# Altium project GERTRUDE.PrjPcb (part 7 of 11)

## Sheet MICROCONTROLLER.SchDoc: Microcontroller
size A3; SheetNumber: 11; SheetTotal: 51
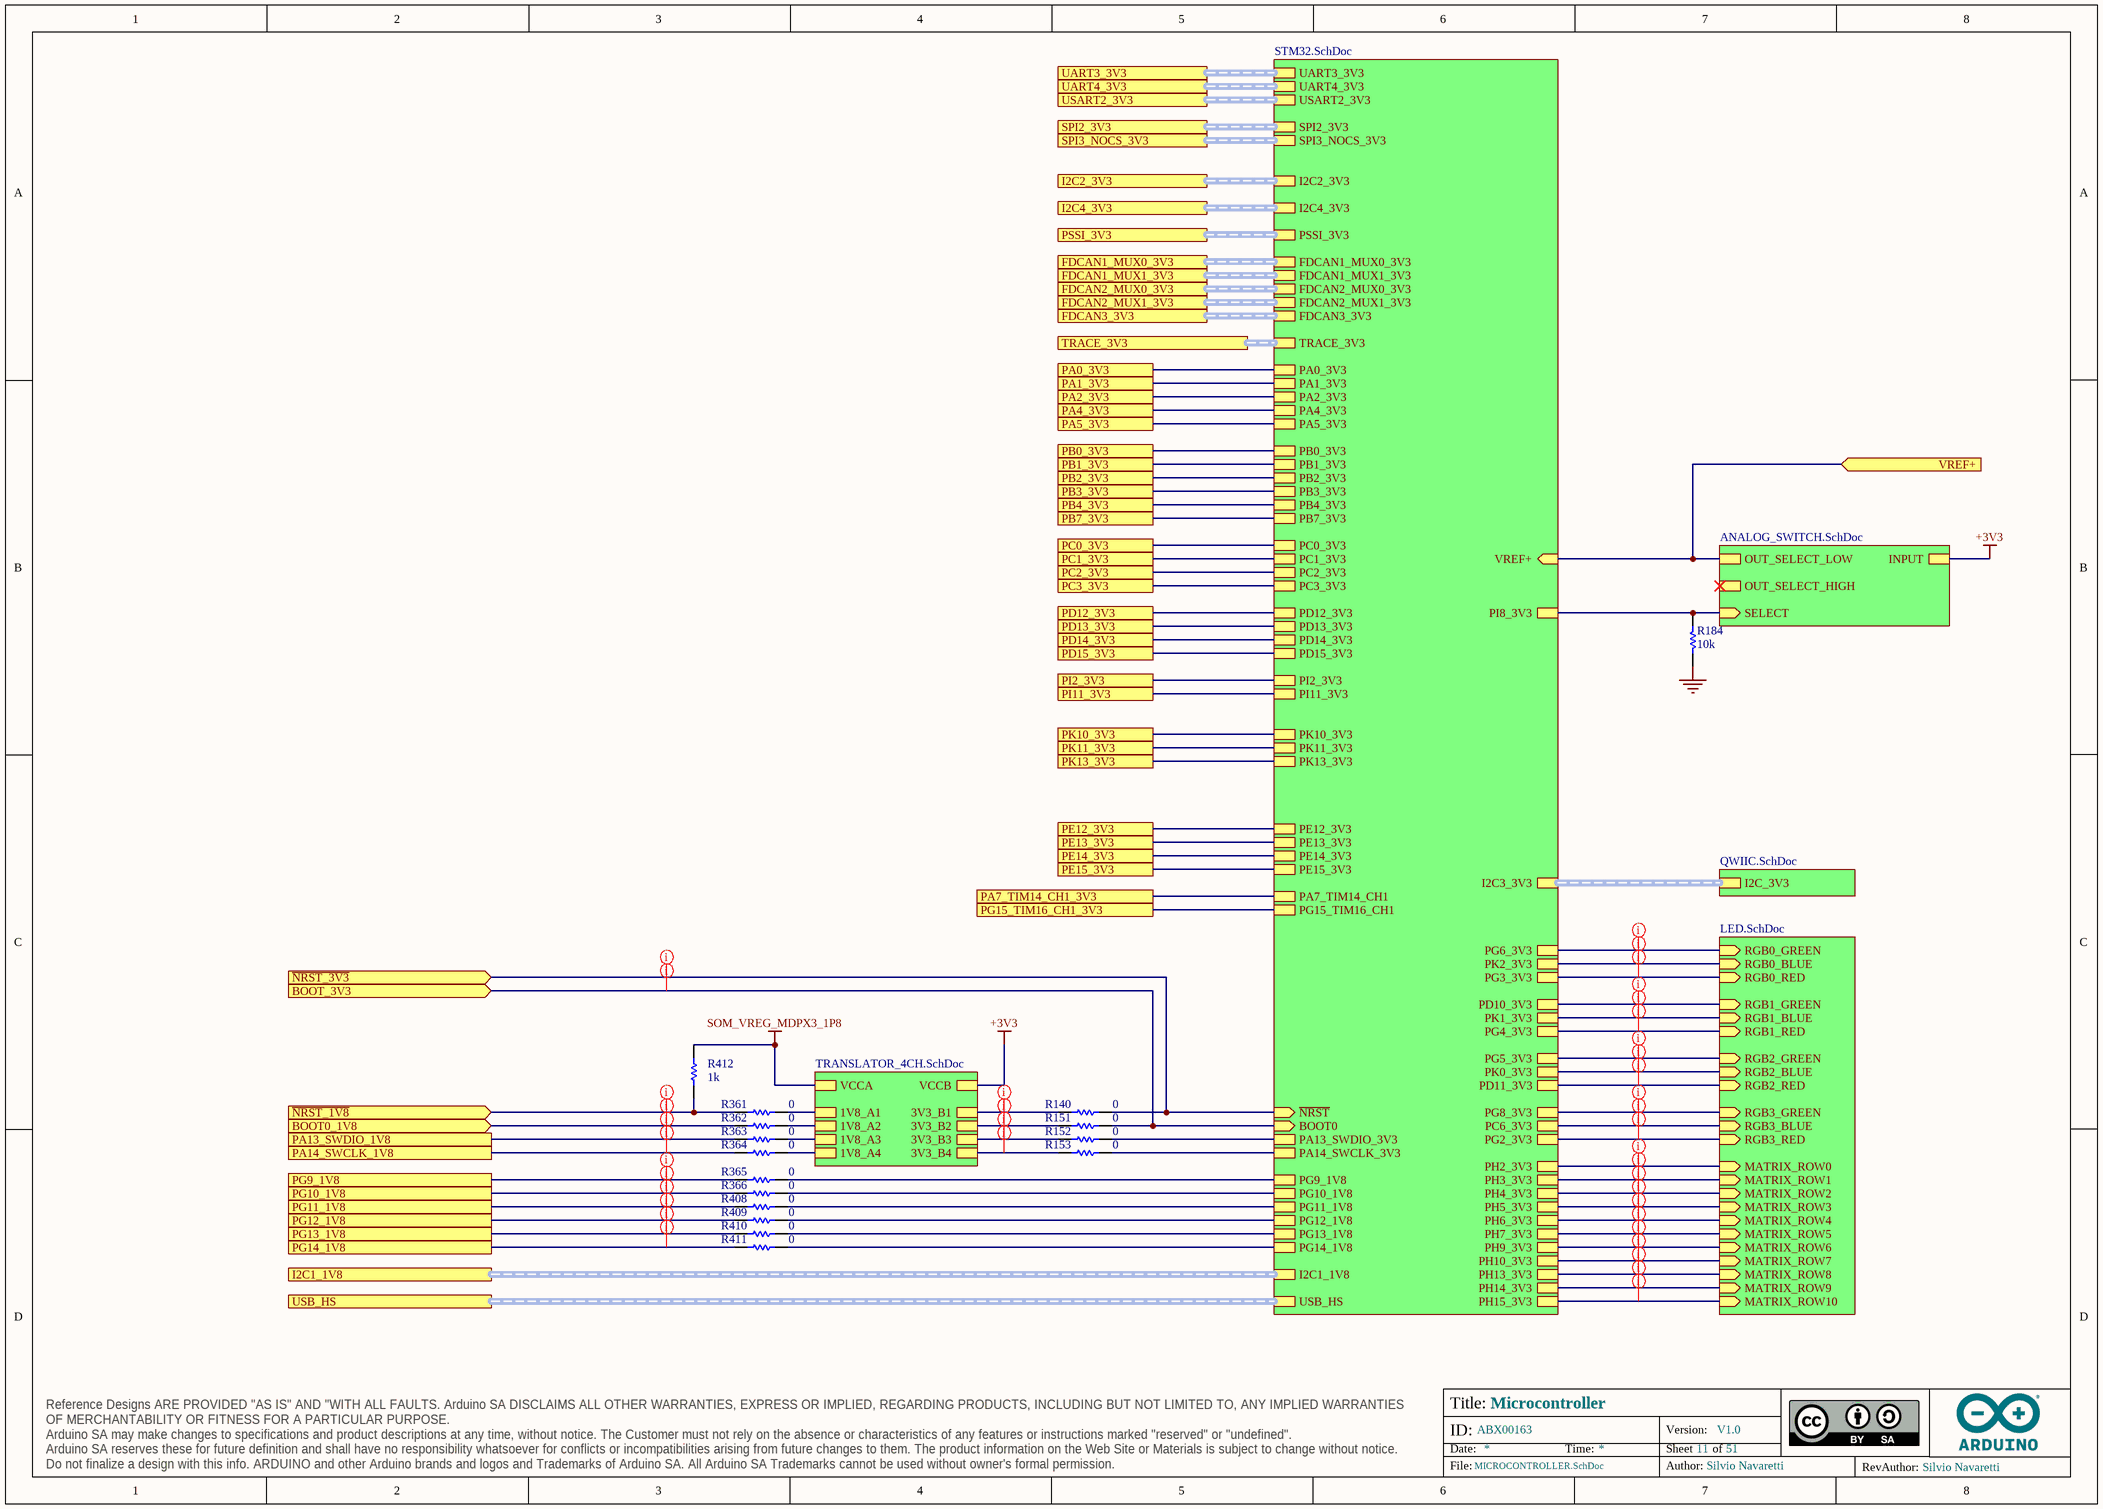
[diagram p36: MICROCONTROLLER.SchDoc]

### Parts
R140  value 0  [RES-0201]  (hidden comment: CRCW02010000Z0ED)
R151  value 0  [RES-0201]  (hidden comment: CRCW02010000Z0ED)
R152  value 0  [RES-0201]  (hidden comment: CRCW02010000Z0ED)
R153  value 0  [RES-0201]  (hidden comment: CRCW02010000Z0ED)
R184  value 10k  [RES-0201]  (hidden comment: RC0201FR-0710KL)
R361  value 0  [RES-0201]  (hidden comment: CRCW02010000Z0ED)
R362  value 0  [RES-0201]  (hidden comment: CRCW02010000Z0ED)
R363  value 0  [RES-0201]  (hidden comment: CRCW02010000Z0ED)
R364  value 0  [RES-0201]  (hidden comment: CRCW02010000Z0ED)
R365  value 0  [RES-0201]  (hidden comment: CRCW02010000Z0ED)
R366  value 0  [RES-0201]  (hidden comment: CRCW02010000Z0ED)
R408  value 0  [RES-0201]  (hidden comment: CRCW02010000Z0ED)
R409  value 0  [RES-0201]  (hidden comment: CRCW02010000Z0ED)
R410  value 0  [RES-0201]  (hidden comment: CRCW02010000Z0ED)
R411  value 0  [RES-0201]  (hidden comment: CRCW02010000Z0ED)
R412  value 1k  [RES-0201]  (hidden comment: RC0201FR-071KL)

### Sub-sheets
U_ANALOG_SWITCH = ANALOG_SWITCH.SchDoc: SELECT (in), OUT_SELECT_LOW, OUT_SELECT_HIGH, INPUT
U_LED = LED.SchDoc: RGB0_GREEN (in), RGB0_BLUE (in), RGB0_RED (in), RGB1_GREEN (in), RGB1_BLUE (in), RGB1_RED (in), RGB2_GREEN (in), RGB2_BLUE (in), RGB2_RED (in), RGB3_GREEN (in), RGB3_BLUE (in), RGB3_RED (in), MATRIX_ROW0 (in), MATRIX_ROW1 (in), MATRIX_ROW2 (in), MATRIX_ROW3 (in), MATRIX_ROW4 (in), MATRIX_ROW5 (in), MATRIX_ROW6 (in), MATRIX_ROW7 (in), MATRIX_ROW8 (in), MATRIX_ROW9 (in), MATRIX_ROW10 (in)
U_QWIIC = QWIIC.SchDoc: I2C_3V3 (harness I2C)
U_STM32 = STM32.SchDoc: USB_HS (harness SOM_MD_USB1), ~{NRST} (in), BOOT0 (in), UART3_3V3 (harness UART), PB2_3V3, PB3_3V3, FDCAN2_MUX0_3V3 (harness CAN), PB0_3V3, PB1_3V3, PB4_3V3, PB7_3V3, SPI2_3V3 (harness SPI), PA0_3V3, PA1_3V3, I2C2_3V3 (harness I2C), PA2_3V3, UART4_3V3 (harness UART), PSSI_3V3 (harness PSSI), PA4_3V3, PA5_3V3, PE12_3V3, PE13_3V3, PE14_3V3, PE15_3V3, FDCAN1_MUX0_3V3 (harness CAN), FDCAN2_MUX1_3V3 (harness CAN), PC0_3V3, PC1_3V3, PC2_3V3, PC3_3V3, PH2_3V3, PH3_3V3, PH4_3V3, PH5_3V3, PH6_3V3, PH7_3V3, PH9_3V3, PH13_3V3, PH14_3V3, PH15_3V3, VREF+ (in), SPI3_NOCS_3V3 (harness JSPI_SPI), I2C4_3V3 (harness I2C), PG9_1V8, PG10_1V8, PG11_1V8, PG12_1V8, PG13_1V8, PG14_1V8, I2C3_3V3 (harness I2C), I2C1_1V8 (harness I2C), PA13_SWDIO_3V3, PA14_SWCLK_3V3, TRACE_3V3 (harness MCU_TRACE), USART2_3V3 (harness UART), PA7_TIM14_CH1, PG15_TIM16_CH1, FDCAN3_3V3 (harness CAN), FDCAN1_MUX1_3V3 (harness CAN), PD12_3V3, PD13_3V3, PD14_3V3, PD15_3V3, PI2_3V3, PI11_3V3, PI8_3V3, PG2_3V3, PK0_3V3, PK1_3V3, PK2_3V3, PD10_3V3, PD11_3V3, PG3_3V3, PG4_3V3, PG5_3V3, PG6_3V3, PC6_3V3, PG8_3V3, PH10_3V3, PK13_3V3, PK10_3V3, PK11_3V3
U_TRANSLATOR_4CH = TRANSLATOR_4CH.SchDoc: 1V8_A1, 1V8_A2, 1V8_A3, 1V8_A4, 3V3_B1, 3V3_B2, 3V3_B3, 3V3_B4, VCCA, VCCB

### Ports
BOOT0_1V8 (in), BOOT_3V3 (in), FDCAN1_MUX0_3V3, FDCAN1_MUX1_3V3, FDCAN2_MUX0_3V3, FDCAN2_MUX1_3V3, FDCAN3_3V3, I2C1_1V8, I2C2_3V3, I2C4_3V3, PA0_3V3, PA1_3V3, PA2_3V3, PA4_3V3, PA5_3V3, PA7_TIM14_CH1_3V3, PA13_SWDIO_1V8, PA14_SWCLK_1V8, PB0_3V3, PB1_3V3, PB2_3V3, PB3_3V3, PB4_3V3, PB7_3V3, PC0_3V3, PC1_3V3, PC2_3V3, PC3_3V3, PD12_3V3, PD13_3V3, PD14_3V3, PD15_3V3, PE12_3V3, PE13_3V3, PE14_3V3, PE15_3V3, PG9_1V8, PG10_1V8, PG11_1V8, PG12_1V8, PG13_1V8, PG14_1V8, PG15_TIM16_CH1_3V3, PI2_3V3, PI11_3V3, PK10_3V3, PK11_3V3, PK13_3V3, PSSI_3V3, SPI2_3V3, SPI3_NOCS_3V3, TRACE_3V3, UART3_3V3, UART4_3V3, USART2_3V3, USB_HS, VREF+ (in), ~{NRST_1V8} (in), ~{NRST_3V3} (in)

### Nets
+3V3: sheet U_ANALOG_SWITCH/INPUT, sheet U_TRANSLATOR_4CH/VCCB
GND: R184.1
SOM_VREG_MDPX3_1P8: R412.1 ; sheet U_TRANSLATOR_4CH/VCCA
BOOT0: R151.1 ; port BOOT_3V3, sheet U_STM32/BOOT0
MD_GPIO_42: R408.2 ; port PG11_1V8
MD_GPIO_47: R362.2 ; port BOOT0_1V8
MD_GPIO_63: R409.2 ; port PG12_1V8
MD_GPIO_69: R365.2 ; port PG9_1V8
MD_GPIO_70: R363.2 ; port PA13_SWDIO_1V8
MD_GPIO_71: R364.2 ; port PA14_SWCLK_1V8
MD_GPIO_78: R361.2 R412.2 ; port ~{NRST_1V8}
MD_GPIO_92: R366.2 ; port PG10_1V8
MD_GPIO_95: R410.2 ; port PG13_1V8
MD_GPIO_96: R411.2 ; port PG14_1V8
NRST: R140.1 ; port ~{NRST_3V3}, sheet U_STM32/~{NRST}
PA0: port PA0_3V3, sheet U_STM32/PA0_3V3
PA1: port PA1_3V3, sheet U_STM32/PA1_3V3
PA2: port PA2_3V3, sheet U_STM32/PA2_3V3
PA4: port PA4_3V3, sheet U_STM32/PA4_3V3
PA5: port PA5_3V3, sheet U_STM32/PA5_3V3
PA7: port PA7_TIM14_CH1_3V3, sheet U_STM32/PA7_TIM14_CH1
PA13: R152.1 ; sheet U_STM32/PA13_SWDIO_3V3
PA14: R153.1 ; sheet U_STM32/PA14_SWCLK_3V3
PB0: port PB0_3V3, sheet U_STM32/PB0_3V3
PB1: port PB1_3V3, sheet U_STM32/PB1_3V3
PB2: port PB2_3V3, sheet U_STM32/PB2_3V3
PB3: port PB3_3V3, sheet U_STM32/PB3_3V3
PB4: port PB4_3V3, sheet U_STM32/PB4_3V3
PB7: port PB7_3V3, sheet U_STM32/PB7_3V3
PC0: port PC0_3V3, sheet U_STM32/PC0_3V3
PC1: port PC1_3V3, sheet U_STM32/PC1_3V3
PC2: port PC2_3V3, sheet U_STM32/PC2_3V3
PC3: port PC3_3V3, sheet U_STM32/PC3_3V3
PC6: sheet U_STM32/PC6_3V3, sheet U_LED/RGB3_BLUE
PD10: sheet U_STM32/PD10_3V3, sheet U_LED/RGB1_GREEN
PD11: sheet U_STM32/PD11_3V3, sheet U_LED/RGB2_RED
PD12: port PD12_3V3, sheet U_STM32/PD12_3V3
PD13: port PD13_3V3, sheet U_STM32/PD13_3V3
PD14: port PD14_3V3, sheet U_STM32/PD14_3V3
PD15: port PD15_3V3, sheet U_STM32/PD15_3V3
PE12: port PE12_3V3, sheet U_STM32/PE12_3V3
PE13: port PE13_3V3, sheet U_STM32/PE13_3V3
PE14: port PE14_3V3, sheet U_STM32/PE14_3V3
PE15: port PE15_3V3, sheet U_STM32/PE15_3V3
PG2: sheet U_STM32/PG2_3V3, sheet U_LED/RGB3_RED
PG3: sheet U_STM32/PG3_3V3, sheet U_LED/RGB0_RED
PG4: sheet U_STM32/PG4_3V3, sheet U_LED/RGB1_RED
PG5: sheet U_STM32/PG5_3V3, sheet U_LED/RGB2_GREEN
PG6: sheet U_STM32/PG6_3V3, sheet U_LED/RGB0_GREEN
PG8: sheet U_STM32/PG8_3V3, sheet U_LED/RGB3_GREEN
PG9: R365.1 ; sheet U_STM32/PG9_1V8
PG10: R366.1 ; sheet U_STM32/PG10_1V8
PG11: R408.1 ; sheet U_STM32/PG11_1V8
PG12: R409.1 ; sheet U_STM32/PG12_1V8
PG13: R410.1 ; sheet U_STM32/PG13_1V8
PG14: R411.1 ; sheet U_STM32/PG14_1V8
PG15: port PG15_TIM16_CH1_3V3, sheet U_STM32/PG15_TIM16_CH1
PH2: sheet U_STM32/PH2_3V3, sheet U_LED/MATRIX_ROW0
PH3: sheet U_STM32/PH3_3V3, sheet U_LED/MATRIX_ROW1
PH4: sheet U_STM32/PH4_3V3, sheet U_LED/MATRIX_ROW2
PH5: sheet U_STM32/PH5_3V3, sheet U_LED/MATRIX_ROW3
PH6: sheet U_STM32/PH6_3V3, sheet U_LED/MATRIX_ROW4
PH7: sheet U_STM32/PH7_3V3, sheet U_LED/MATRIX_ROW5
PH9: sheet U_STM32/PH9_3V3, sheet U_LED/MATRIX_ROW6
PH10: sheet U_STM32/PH10_3V3, sheet U_LED/MATRIX_ROW7
PH13: sheet U_STM32/PH13_3V3, sheet U_LED/MATRIX_ROW8
PH14: sheet U_STM32/PH14_3V3, sheet U_LED/MATRIX_ROW9
PH15: sheet U_STM32/PH15_3V3, sheet U_LED/MATRIX_ROW10
PI2: port PI2_3V3, sheet U_STM32/PI2_3V3
PI8: R184.2 ; sheet U_STM32/PI8_3V3, sheet U_ANALOG_SWITCH/SELECT
PI11: port PI11_3V3, sheet U_STM32/PI11_3V3
PK0: sheet U_STM32/PK0_3V3, sheet U_LED/RGB2_BLUE
PK1: sheet U_STM32/PK1_3V3, sheet U_LED/RGB1_BLUE
PK2: sheet U_STM32/PK2_3V3, sheet U_LED/RGB0_BLUE
PK10: port PK10_3V3, sheet U_STM32/PK10_3V3
PK11: port PK11_3V3, sheet U_STM32/PK11_3V3
PK13: port PK13_3V3, sheet U_STM32/PK13_3V3
NetC107_2: port VREF+, sheet U_STM32/VREF+, sheet U_ANALOG_SWITCH/OUT_SELECT_LOW
NetR140_2: R140.2 ; sheet U_TRANSLATOR_4CH/3V3_B1
NetR151_2: R151.2 ; sheet U_TRANSLATOR_4CH/3V3_B2
NetR152_2: R152.2 ; sheet U_TRANSLATOR_4CH/3V3_B3
NetR153_2: R153.2 ; sheet U_TRANSLATOR_4CH/3V3_B4
NetR361_1: R361.1 ; sheet U_TRANSLATOR_4CH/1V8_A1
NetR362_1: R362.1 ; sheet U_TRANSLATOR_4CH/1V8_A2
NetR363_1: R363.1 ; sheet U_TRANSLATOR_4CH/1V8_A3
NetR364_1: R364.1 ; sheet U_TRANSLATOR_4CH/1V8_A4

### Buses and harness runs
harness port FDCAN1_MUX0_3V3 = sheet U_STM32/FDCAN1_MUX0_3V3
harness port FDCAN1_MUX1_3V3 = sheet U_STM32/FDCAN1_MUX1_3V3
harness port FDCAN2_MUX0_3V3 = sheet U_STM32/FDCAN2_MUX0_3V3
harness port FDCAN2_MUX1_3V3 = sheet U_STM32/FDCAN2_MUX1_3V3
harness port FDCAN3_3V3 = sheet U_STM32/FDCAN3_3V3
harness port I2C1_1V8 = sheet U_STM32/I2C1_1V8
harness port I2C2_3V3 = sheet U_STM32/I2C2_3V3
harness port I2C4_3V3 = sheet U_STM32/I2C4_3V3
harness port PSSI_3V3 = sheet U_STM32/PSSI_3V3
harness port SPI2_3V3 = sheet U_STM32/SPI2_3V3
harness port SPI3_NOCS_3V3 = sheet U_STM32/SPI3_NOCS_3V3
harness port TRACE_3V3 = sheet U_STM32/TRACE_3V3
harness port UART3_3V3 = sheet U_STM32/UART3_3V3
harness port UART4_3V3 = sheet U_STM32/UART4_3V3
harness port USART2_3V3 = sheet U_STM32/USART2_3V3
harness port USB_HS = sheet U_STM32/USB_HS
harness sheet U_QWIIC/I2C_3V3 = sheet U_STM32/I2C3_3V3

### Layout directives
net class MICROCONTROLLER: BOOT0, MD_GPIO_42, MD_GPIO_47, MD_GPIO_63, MD_GPIO_69, MD_GPIO_70, MD_GPIO_71, MD_GPIO_78, MD_GPIO_92, MD_GPIO_95, MD_GPIO_96, NetR140_2, NetR151_2, NetR152_2, NetR153_2, NRST
net class MICROCONTROLLER_RGB: PC6, PD10, PD11, PG2, PG3, PG4, PG5, PG6, PG8, PK0, PK1, PK2
net class MICROCONTROLLER_MATRIX: PH2, PH3, PH4, PH5, PH6, PH7, PH9, PH10, PH13, PH14, PH15

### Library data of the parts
R140 R151-R153 R361-R366 R408-R411 = R0140-A.21: RES CHIP 0201 0R; Manufacturer: Vishay; Temperature coefficient: 0ppm; Code Arduino: R0140; Power: 50mW; Tolerance: 0%
R184 = R0145-A.21: RES CHIP 0201 10k 1% 1/20W; Manufacturer: Yageo; Power: 50mW; Temperature coefficient: 200ppm; Code Arduino: R0145
R412 = R0195-A.22: RES CHIP 0201 1k 1% 1/20W; Manufacturer: Yageo; Power: 50mW; Temperature coefficient: 200ppm; Code Arduino: R0195

## Sheet STM32.SchDoc: STM32
size A3; SheetNumber: 12; SheetTotal: 51
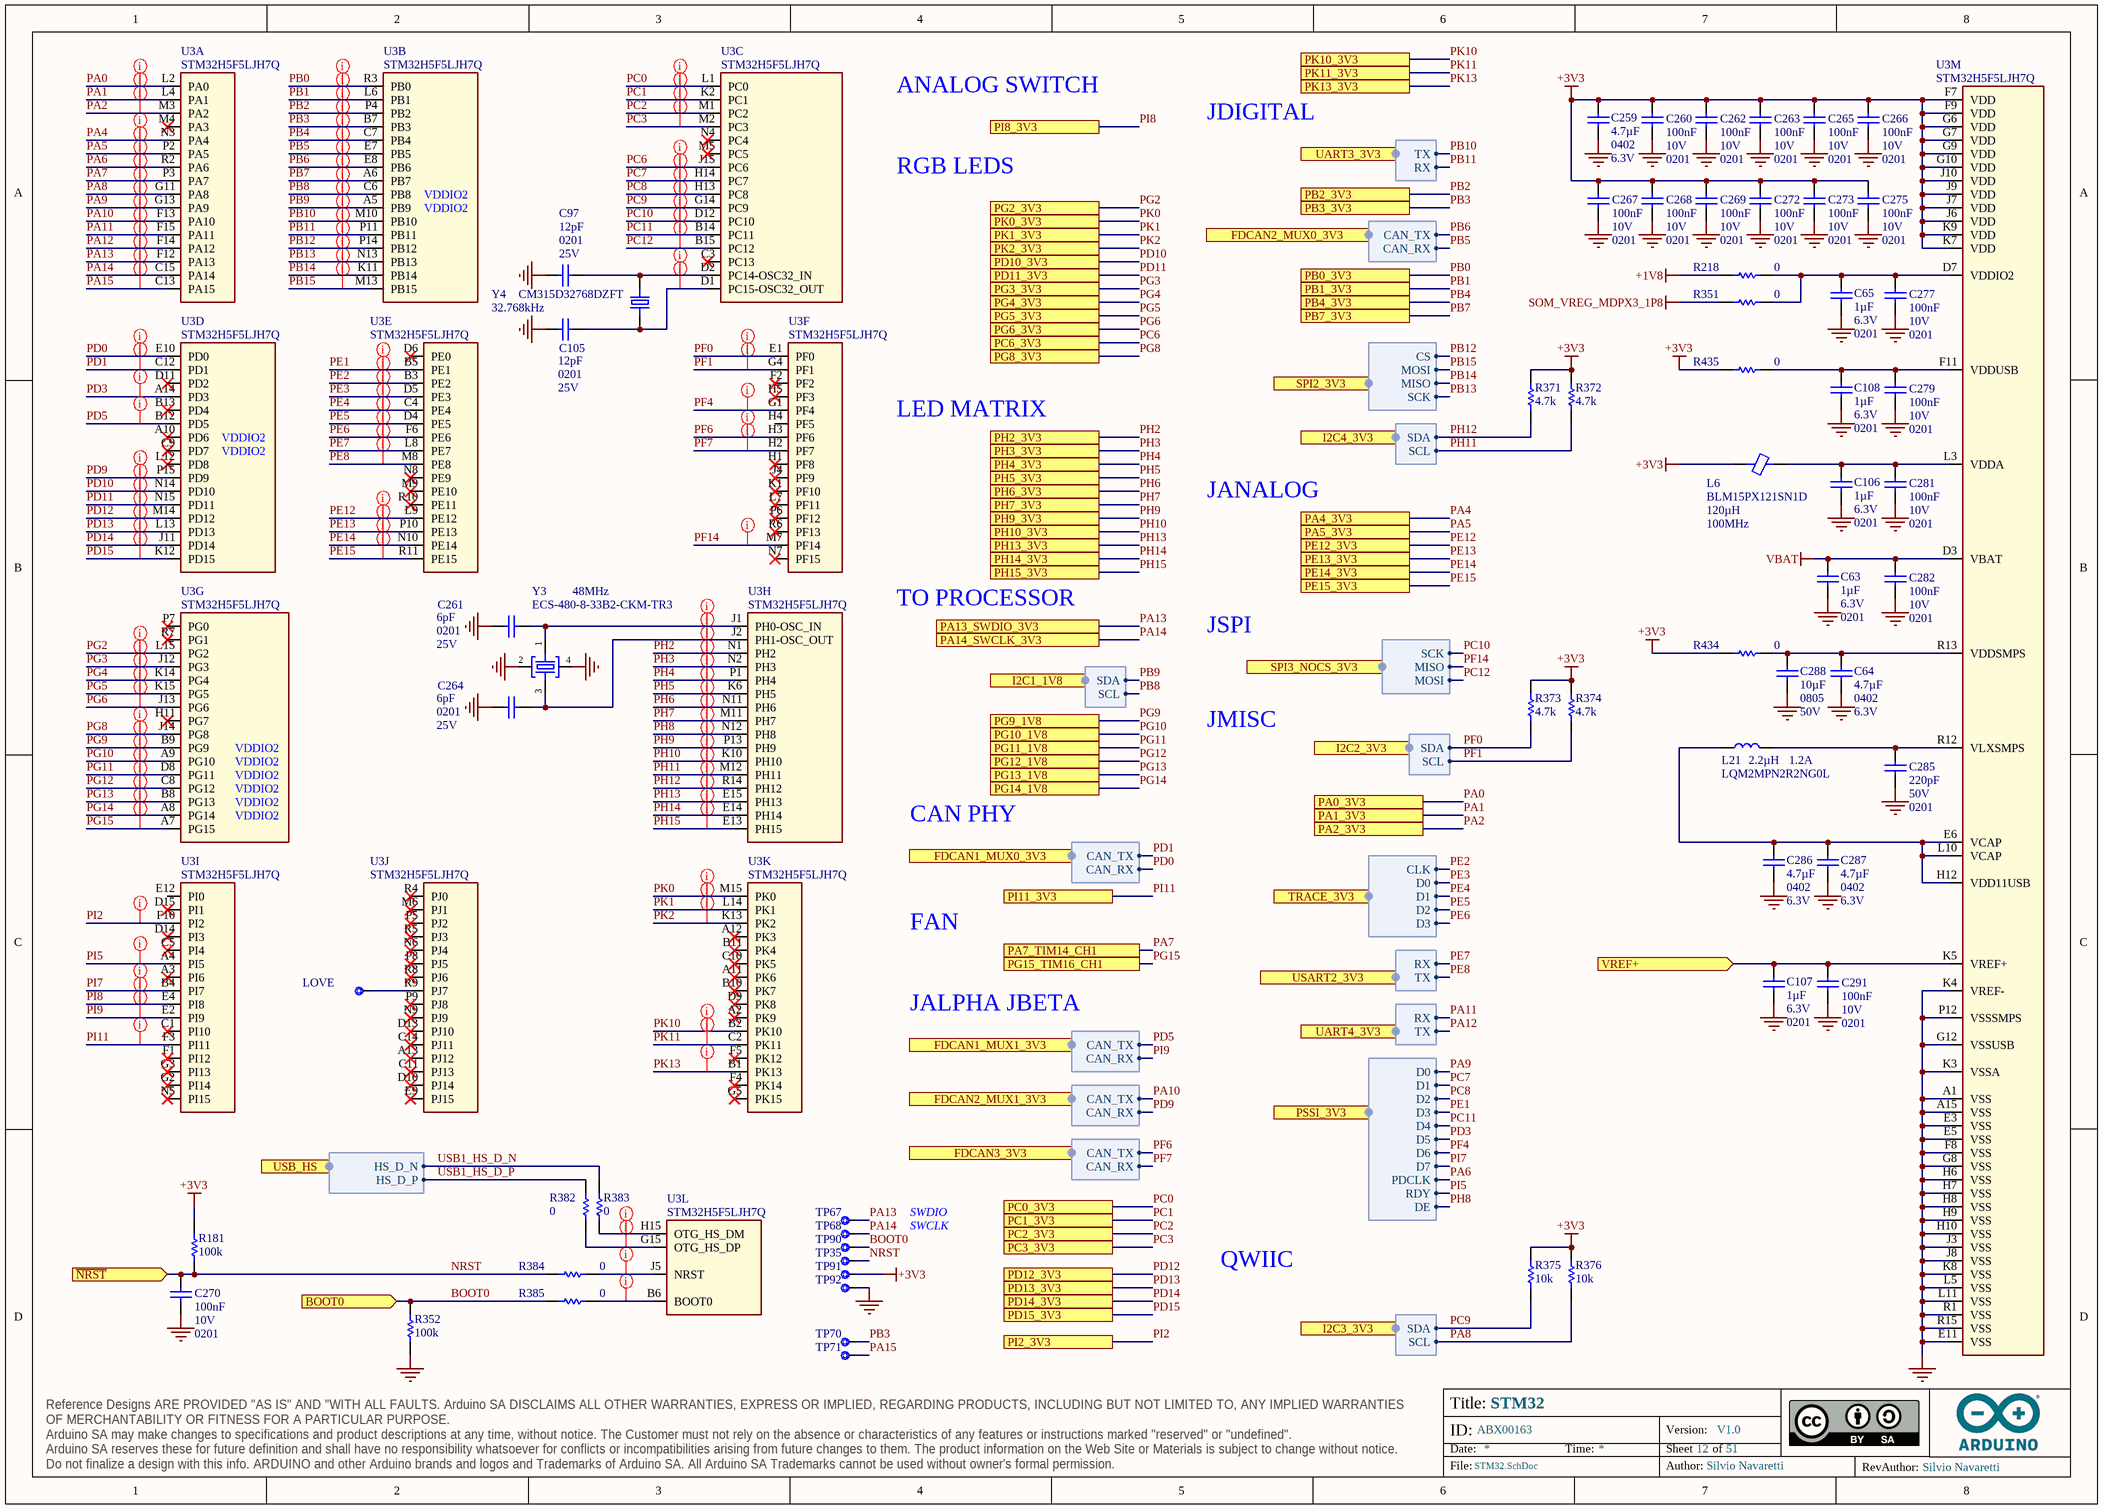
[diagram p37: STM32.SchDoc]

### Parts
C63  value 1µF  Voltage: 6.3V  Case Code (Imperial): 0201  [CAP-0201]  (hidden comment: GRM033R60J105MEA2D)
C64  value 4.7µF  Case Code (Imperial): 0402  Voltage: 6.3V  [CAP-0402]  (hidden comment: C1005A475M6R3NT)
C65  value 1µF  Voltage: 6.3V  Case Code (Imperial): 0201  [CAP-0201]  (hidden comment: GRM033R60J105MEA2D)
C97  value 12pF  Case Code (Imperial): 0201  Voltage: 25V  [CAP-0201]  (hidden comment: GRM0335C1E120JA01J)
C105  value 12pF  Case Code (Imperial): 0201  Voltage: 25V  [CAP-0201]  (hidden comment: GRM0335C1E120JA01J)
C106  value 1µF  Voltage: 6.3V  Case Code (Imperial): 0201  [CAP-0201]  (hidden comment: GRM033R60J105MEA2D)
C107  value 1µF  Voltage: 6.3V  Case Code (Imperial): 0201  [CAP-0201]  (hidden comment: GRM033R60J105MEA2D)
C108  value 1µF  Voltage: 6.3V  Case Code (Imperial): 0201  [CAP-0201]  (hidden comment: GRM033R60J105MEA2D)
C259  value 4.7µF  Case Code (Imperial): 0402  Voltage: 6.3V  [CAP-0402]  (hidden comment: C1005A475M6R3NT)
C260  value 100nF  Voltage: 10V  Case Code (Imperial): 0201  [CAP-0201]  (hidden comment: CL03A104KP3NNNC)
C261  value 6pF  Case Code (Imperial): 0201  Voltage: 25V  [CAP-0201]  (hidden comment: GRM0335C1E6R0CA01D)
C262  value 100nF  Voltage: 10V  Case Code (Imperial): 0201  [CAP-0201]  (hidden comment: CL03A104KP3NNNC)
C263  value 100nF  Voltage: 10V  Case Code (Imperial): 0201  [CAP-0201]  (hidden comment: CL03A104KP3NNNC)
C264  value 6pF  Case Code (Imperial): 0201  Voltage: 25V  [CAP-0201]  (hidden comment: GRM0335C1E6R0CA01D)
C265  value 100nF  Voltage: 10V  Case Code (Imperial): 0201  [CAP-0201]  (hidden comment: CL03A104KP3NNNC)
C266  value 100nF  Voltage: 10V  Case Code (Imperial): 0201  [CAP-0201]  (hidden comment: CL03A104KP3NNNC)
C267  value 100nF  Voltage: 10V  Case Code (Imperial): 0201  [CAP-0201]  (hidden comment: CL03A104KP3NNNC)
C268  value 100nF  Voltage: 10V  Case Code (Imperial): 0201  [CAP-0201]  (hidden comment: CL03A104KP3NNNC)
C269  value 100nF  Voltage: 10V  Case Code (Imperial): 0201  [CAP-0201]  (hidden comment: CL03A104KP3NNNC)
C270  value 100nF  Voltage: 10V  Case Code (Imperial): 0201  [CAP-0201]  (hidden comment: CL03A104KP3NNNC)
C272  value 100nF  Voltage: 10V  Case Code (Imperial): 0201  [CAP-0201]  (hidden comment: CL03A104KP3NNNC)
C273  value 100nF  Voltage: 10V  Case Code (Imperial): 0201  [CAP-0201]  (hidden comment: CL03A104KP3NNNC)
C275  value 100nF  Voltage: 10V  Case Code (Imperial): 0201  [CAP-0201]  (hidden comment: CL03A104KP3NNNC)
C277  value 100nF  Voltage: 10V  Case Code (Imperial): 0201  [CAP-0201]  (hidden comment: CL03A104KP3NNNC)
C279  value 100nF  Voltage: 10V  Case Code (Imperial): 0201  [CAP-0201]  (hidden comment: CL03A104KP3NNNC)
C281  value 100nF  Voltage: 10V  Case Code (Imperial): 0201  [CAP-0201]  (hidden comment: CL03A104KP3NNNC)
C282  value 100nF  Voltage: 10V  Case Code (Imperial): 0201  [CAP-0201]  (hidden comment: CL03A104KP3NNNC)
C285  value 220pF  Voltage: 50V  Case Code (Imperial): 0201  [CAP-0201]  (hidden comment: GRM033R71H221KA12D)
C286  value 4.7µF  Case Code (Imperial): 0402  Voltage: 6.3V  [CAP-0402]  (hidden comment: C1005A475M6R3NT)
C287  value 4.7µF  Case Code (Imperial): 0402  Voltage: 6.3V  [CAP-0402]  (hidden comment: C1005A475M6R3NT)
C288  value 10µF  Case Code (Imperial): 0805  Voltage: 50V  [CAP-0805]  (hidden comment: GRM21BR61H106ME43L)
C291  value 100nF  Voltage: 10V  Case Code (Imperial): 0201  [CAP-0201]  (hidden comment: CL03A104KP3NNNC)
L6  BLM15PX121SN1D  Inductance: 120µH  Test Frequency: 100MHz  [L-0402]
L21  LQM2MPN2R2NG0L  Current: 1.2A  Inductance: 2.2µH  [LQM2MPN2R2NG0L]
LOVE  Test point 1.00mm  [TP-1.00MM]  (value not drawn)  (no BOM)
R181  value 100k  [RES-0201]  (hidden comment: RC0201FR-07100KL)
R218  value 0  [RES-0201]  (hidden comment: CRCW02010000Z0ED)
R351  value 0  [RES-0201]  (hidden comment: CRCW02010000Z0ED)
R352  value 100k  [RES-0201]  (hidden comment: RC0201FR-07100KL)
R371  value 4.7k  [RES-0201]  (hidden comment: RC0201FR-074K7L)
R372  value 4.7k  [RES-0201]  (hidden comment: RC0201FR-074K7L)
R373  value 4.7k  [RES-0201]  (hidden comment: RC0201FR-074K7L)
R374  value 4.7k  [RES-0201]  (hidden comment: RC0201FR-074K7L)
R375  value 10k  [RES-0201]  (hidden comment: RC0201FR-0710KL)
R376  value 10k  [RES-0201]  (hidden comment: RC0201FR-0710KL)
R382  value 0  [RES-0201]  (hidden comment: CRCW02010000Z0ED)
R383  value 0  [RES-0201]  (hidden comment: CRCW02010000Z0ED)
R384  value 0  [RES-0201]  (hidden comment: CRCW02010000Z0ED)
R385  value 0  [RES-0201]  (hidden comment: CRCW02010000Z0ED)
R434  value 0  [RES-0201]  (hidden comment: CRCW02010000Z0ED)
R435  value 0  [RES-0201]  (hidden comment: CRCW02010000Z0ED)
TP35  Test point 1.00mm  [TP-1.00MM]  (value not drawn)  (no BOM)
TP67  Test point 1.00mm  [TP-1.00MM]  (value not drawn)  (no BOM)
TP68  Test point 1.00mm  [TP-1.00MM]  (value not drawn)  (no BOM)
TP70  Test point 1.00mm  [TP-1.00MM]  (value not drawn)  (no BOM)
TP71  Test point 1.00mm  [TP-1.00MM]  (value not drawn)  (no BOM)
TP90  Test point 1.00mm  [TP-1.00MM]  (value not drawn)  (no BOM)
TP91  Test point 1.00mm  [TP-1.00MM]  (value not drawn)  (no BOM)
TP92  Test point 1.00mm  [TP-1.00MM]  (value not drawn)  (no BOM)
U3  STM32H5F5LJH7Q  [BGA225C80P15X15_1300X1300X120]  (parts A,B,C,D,E,F,G,H,I,J,K,L,M of 13)
Y3  ECS-480-8-33B2-CKM-TR3  Frequency: 48MHz  [CRYSTAL3.2X2.5]
Y4  CM315D32768DZFT  Frequency: 32.768kHz  [ABS07]

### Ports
BOOT0 (in), FDCAN1_MUX0_3V3 (harness CAN), FDCAN1_MUX1_3V3 (harness CAN), FDCAN2_MUX0_3V3 (harness CAN), FDCAN2_MUX1_3V3 (harness CAN), FDCAN3_3V3 (harness CAN), I2C1_1V8 (harness I2C), I2C2_3V3 (harness I2C), I2C3_3V3 (harness I2C), I2C4_3V3 (harness I2C), PA0_3V3, PA1_3V3, PA2_3V3, PA4_3V3, PA5_3V3, PA7_TIM14_CH1, PA13_SWDIO_3V3, PA14_SWCLK_3V3, PB0_3V3, PB1_3V3, PB2_3V3, PB3_3V3, PB4_3V3, PB7_3V3, PC0_3V3, PC1_3V3, PC2_3V3, PC3_3V3, PC6_3V3, PD10_3V3, PD11_3V3, PD12_3V3, PD13_3V3, PD14_3V3, PD15_3V3, PE12_3V3, PE13_3V3, PE14_3V3, PE15_3V3, PG2_3V3, PG3_3V3, PG4_3V3, PG5_3V3, PG6_3V3, PG8_3V3, PG9_1V8, PG10_1V8, PG11_1V8, PG12_1V8, PG13_1V8, PG14_1V8, PG15_TIM16_CH1, PH2_3V3, PH3_3V3, PH4_3V3, PH5_3V3, PH6_3V3, PH7_3V3, PH9_3V3, PH10_3V3, PH13_3V3, PH14_3V3, PH15_3V3, PI2_3V3, PI8_3V3, PI11_3V3, PK0_3V3, PK1_3V3, PK2_3V3, PK10_3V3, PK11_3V3, PK13_3V3, PSSI_3V3 (harness PSSI), SPI2_3V3 (harness SPI), SPI3_NOCS_3V3 (harness JSPI_SPI), TRACE_3V3 (harness MCU_TRACE), UART3_3V3 (harness UART), UART4_3V3 (harness UART), USART2_3V3 (harness UART), USB_HS (harness SOM_MD_USB1), VREF+ (in), ~{NRST} (in)

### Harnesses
SPI: SCK, MISO, MOSI, CS
UART: TX, RX
I2C: SDA, SCL
CAN: CAN_TX, CAN_RX
PSSI: D0, D1, D2, D3, D4, D5, D6, D7, PDCLK, RDY, DE
JSPI_SPI: SCK, MISO, MOSI
MCU_TRACE: CLK, D0, D1, D2, D3
SOM_MD_USB1: HS_D_P, HS_D_N

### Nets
+1V8: R218.1
+3V3: C259.1 C260.2 C262.2 C263.2 C265.2 C266.2 C267.2 C268.2 C269.2 C272.2 C273.2 C275.2 L6.1 R181.2 R371.2 R372.2 R373.2 R374.2 R375.2 R376.2 R434.1 R435.1 TP91.X U3.F7(VDD) U3.F9(VDD) U3.G6(VDD) U3.G7(VDD) U3.G9(VDD) U3.G10(VDD) U3.J6(VDD) U3.J7(VDD) U3.J9(VDD) U3.J10(VDD) U3.K7(VDD) U3.K9(VDD)
GND: C63.1 C64.2 C65.1 C97.2 C105.2 C106.1 C107.1 C108.1 C259.2 C260.1 C261.2 C262.1 C263.1 C264.2 C265.1 C266.1 C267.1 C268.1 C269.1 C270.1 C272.1 C273.1 C275.1 C277.1 C279.1 C281.1 C282.1 C285.1 C286.2 C287.2 C288.2 C291.1 R352.1 TP92.X U3.A1(VSS) U3.A15(VSS) U3.E3(VSS) U3.E5(VSS) U3.E11(VSS) U3.F8(VSS) U3.G8(VSS) U3.G12(VSSUSB) U3.H6(VSS) U3.H7(VSS) U3.H8(VSS) U3.H9(VSS) U3.H10(VSS) U3.J3(VSS) U3.J8(VSS) U3.K3(VSSA) U3.K4(VREF-) U3.K8(VSS) U3.L5(VSS) U3.L11(VSS) U3.P12(VSSSMPS) U3.R1(VSS) U3.R15(VSS) Y3.2 Y3.4
SOM_VREG_MDPX3_1P8: R351.1
VBAT: C63.2 C282.2 U3.D3(VBAT)
BOOT0: R352.2 R385.1 TP90.X ; port BOOT0
NRST: C270.2 R181.1 R384.1 TP35.X ; port ~{NRST}
PA0: U3.L2(PA0) ; port PA0_3V3
PA1: U3.L4(PA1) ; port PA1_3V3
PA2: U3.M3(PA2) ; port PA2_3V3
PA4: U3.N3(PA4) ; port PA4_3V3
PA5: U3.P2(PA5) ; port PA5_3V3
PA6: U3.R2(PA6) ; port PSSI_3V3.PDCLK
PA7: U3.P3(PA7) ; port PA7_TIM14_CH1
PA8: R376.1 U3.G11(PA8) ; port I2C3_3V3.SCL
PA9: U3.G13(PA9) ; port PSSI_3V3.D0
PA10: U3.F13(PA10) ; port FDCAN2_MUX1_3V3.CAN_TX
PA11: U3.F15(PA11) ; port UART4_3V3.RX
PA12: U3.F14(PA12) ; port UART4_3V3.TX
PA13: TP67.X U3.F12(PA13) ; port PA13_SWDIO_3V3
PA14: TP68.X U3.C15(PA14) ; port PA14_SWCLK_3V3
PA15: TP71.X U3.C13(PA15)  [project net PA15_12]
PB0: U3.R3(PB0) ; port PB0_3V3
PB1: U3.L6(PB1) ; port PB1_3V3
PB2: U3.P4(PB2) ; port PB2_3V3
PB3: TP70.X U3.B7(PB3) ; port PB3_3V3
PB4: U3.C7(PB4) ; port PB4_3V3
PB5: U3.E7(PB5) ; port FDCAN2_MUX0_3V3.CAN_RX
PB6: U3.E8(PB6) ; port FDCAN2_MUX0_3V3.CAN_TX
PB7: U3.A6(PB7) ; port PB7_3V3
PB8: U3.C6(PB8) ; port I2C1_1V8.SCL  [project net MD_CCI_I2C3.SCL]
PB9: U3.A5(PB9) ; port I2C1_1V8.SDA  [project net MD_CCI_I2C3.SDA]
PB10: U3.M10(PB10) ; port UART3_3V3.TX
PB11: U3.P11(PB11) ; port UART3_3V3.RX
PB12: U3.P14(PB12) ; port SPI2_3V3.CS
PB13: U3.N13(PB13) ; port SPI2_3V3.SCK
PB14: U3.K11(PB14) ; port SPI2_3V3.MISO
PB15: U3.M13(PB15) ; port SPI2_3V3.MOSI
PC0: U3.L1(PC0) ; port PC0_3V3
PC1: U3.K2(PC1) ; port PC1_3V3
PC2: U3.M1(PC2) ; port PC2_3V3
PC3: U3.M2(PC3) ; port PC3_3V3
PC6: U3.J15(PC6) ; port PC6_3V3
PC7: U3.H14(PC7) ; port PSSI_3V3.D1
PC8: U3.H13(PC8) ; port PSSI_3V3.D2
PC9: R375.1 U3.G14(PC9) ; port I2C3_3V3.SDA
PC10: U3.D12(PC10) ; port SPI3_NOCS_3V3.SCK
PC11: U3.B14(PC11) ; port PSSI_3V3.D4
PC12: U3.B15(PC12) ; port SPI3_NOCS_3V3.MOSI
PD0: U3.E10(PD0) ; port FDCAN1_MUX0_3V3.CAN_RX
PD1: U3.C12(PD1) ; port FDCAN1_MUX0_3V3.CAN_TX
PD3: U3.A14(PD3) ; port PSSI_3V3.D5
PD5: U3.B12(PD5) ; port FDCAN1_MUX1_3V3.CAN_TX
PD9: U3.P15(PD9) ; port FDCAN2_MUX1_3V3.CAN_RX
PD10: U3.N14(PD10) ; port PD10_3V3
PD11: U3.N15(PD11) ; port PD11_3V3
PD12: U3.M14(PD12) ; port PD12_3V3
PD13: U3.L13(PD13) ; port PD13_3V3
PD14: U3.J11(PD14) ; port PD14_3V3
PD15: U3.K12(PD15) ; port PD15_3V3
PE1: U3.B5(PE1) ; port PSSI_3V3.D3
PE2: U3.B3(PE2) ; port TRACE_3V3.CLK
PE3: U3.D5(PE3) ; port TRACE_3V3.D0
PE4: U3.C4(PE4) ; port TRACE_3V3.D1
PE5: U3.D4(PE5) ; port TRACE_3V3.D2
PE6: U3.F6(PE6) ; port TRACE_3V3.D3
PE7: U3.L8(PE7) ; port USART2_3V3.RX
PE8: U3.M8(PE8) ; port USART2_3V3.TX
PE12: U3.L9(PE12) ; port PE12_3V3
PE13: U3.P10(PE13) ; port PE13_3V3
PE14: U3.N10(PE14) ; port PE14_3V3
PE15: U3.R11(PE15) ; port PE15_3V3
PF0: R373.1 U3.E1(PF0) ; port I2C2_3V3.SDA
PF1: R374.1 U3.G4(PF1) ; port I2C2_3V3.SCL
PF4: U3.G1(PF4) ; port PSSI_3V3.D6
PF6: U3.H3(PF6) ; port FDCAN3_3V3.CAN_TX
PF7: U3.H2(PF7) ; port FDCAN3_3V3.CAN_RX
PF14: U3.M7(PF14) ; port SPI3_NOCS_3V3.MISO
PG2: U3.L15(PG2) ; port PG2_3V3
PG3: U3.J12(PG3) ; port PG3_3V3
PG4: U3.K14(PG4) ; port PG4_3V3
PG5: U3.K15(PG5) ; port PG5_3V3
PG6: U3.J13(PG6) ; port PG6_3V3
PG8: U3.J14(PG8) ; port PG8_3V3
PG9: U3.B9(PG9) ; port PG9_1V8
PG10: U3.A9(PG10) ; port PG10_1V8
PG11: U3.D8(PG11) ; port PG11_1V8
PG12: U3.C8(PG12) ; port PG12_1V8
PG13: U3.B8(PG13) ; port PG13_1V8
PG14: U3.A8(PG14) ; port PG14_1V8
PG15: U3.A7(PG15) ; port PG15_TIM16_CH1
PH2: U3.N1(PH2) ; port PH2_3V3
PH3: U3.N2(PH3) ; port PH3_3V3
PH4: U3.P1(PH4) ; port PH4_3V3
PH5: U3.K6(PH5) ; port PH5_3V3
PH6: U3.N11(PH6) ; port PH6_3V3
PH7: U3.M11(PH7) ; port PH7_3V3
PH8: U3.N12(PH8) ; port PSSI_3V3.DE
PH9: U3.P13(PH9) ; port PH9_3V3
PH10: U3.K10(PH10) ; port PH10_3V3
PH11: R372.1 U3.M12(PH11) ; port I2C4_3V3.SCL
PH12: R371.1 U3.R14(PH12) ; port I2C4_3V3.SDA
PH13: U3.E15(PH13) ; port PH13_3V3
PH14: U3.E14(PH14) ; port PH14_3V3
PH15: U3.E13(PH15) ; port PH15_3V3
PI2: U3.F10(PI2) ; port PI2_3V3
PI5: U3.A4(PI5) ; port PSSI_3V3.RDY
PI7: U3.B4(PI7) ; port PSSI_3V3.D7
PI8: U3.E4(PI8) ; port PI8_3V3
PI9: U3.E2(PI9) ; port FDCAN1_MUX1_3V3.CAN_RX
PI11: U3.F3(PI11) ; port PI11_3V3
PK0: U3.M15(PK0) ; port PK0_3V3
PK1: U3.L14(PK1) ; port PK1_3V3
PK2: U3.K13(PK2) ; port PK2_3V3
PK10: U3.B2(PK10) ; port PK10_3V3
PK11: U3.C2(PK11) ; port PK11_3V3
PK13: U3.B1(PK13) ; port PK13_3V3
USB1_HS_D_N: R383.1 ; port USB_HS.HS_D_N  [project net MD_USB1_2.0.HS_D_N]
USB1_HS_D_P: R382.1 ; port USB_HS.HS_D_P  [project net MD_USB1_2.0.HS_D_P]
NetC64_1: C64.1 C288.1 R434.2 U3.R13(VDDSMPS)
NetC65_2: C65.2 C277.2 R218.2 R351.2 U3.D7(VDDIO2)
NetC97_1: C97.1 U3.D2(PC14-OSC32_IN) Y4.2
NetC105_1: C105.1 U3.D1(PC15-OSC32_OUT) Y4.1
NetC106_2: C106.2 C281.2 L6.2 U3.L3(VDDA)
NetC107_2: C107.2 C291.2 U3.K5(VREF+) ; port VREF+
NetC108_2: C108.2 C279.2 R435.2 U3.F11(VDDUSB)
NetC261_1: C261.1 U3.J1(PH0-OSC_IN) Y3.1
NetC264_1: C264.1 U3.J2(PH1-OSC_OUT) Y3.3
NetC285_2: C285.2 L21.2 U3.R12(VLXSMPS)
NetC286_1: C286.1 C287.1 L21.1 U3.E6(VCAP) U3.H12(VDD11USB) U3.L10(VCAP)
NetLOVE_X: LOVE.X U3.R9(PJ7)
NetR382_2: R382.2 U3.G15(OTG_HS_DP)
NetR383_2: R383.2 U3.H15(OTG_HS_DM)
NetR384_2: R384.2 U3.J5(NRST)
NetR385_2: R385.2 U3.B6(BOOT0)

Not connected (* = marked no-connect by the designer): U3 A2(PK9)* A3(PI6)* A10(PD6)* A11(PK6)* A12(PK3)* A13(PJ12)* B10(PK7)* B11(PK4)* B13(PD4)* C1(PI10)* C3(PC13)* C5(PI4)* C9(PD7)* C10(PK5)* C11(PJ13)* C14(PJ11)* D6(PE0)* D9(PK8)* D10(PJ14)* D11(PD2)* D13(PJ10)* D14(PI3)* D15(PI1)* E9(PJ15)* E12(PI0) F1(PI12)* F2(PF2)* F4(PK14)* F5(PK12)* G2(PI14)* G3(PI13)* G5(PK15)* H1(PF8)* H4(PF5) H5(PF3)* H11(PG7)* J4(PF9)* K1(PF10)* L7(PF11)* L12(PD8)* M4(PA3)* M5(PC5)* M6(PJ1)* M9(PE10)* N4(PC4)* N5(PI15)* N6(PJ4)* N7(PF15)* N8(PE9)* N9(PJ9)* P5(PJ2)* P6(PF12)* P7(PG0)* P8(PJ5)* P9(PJ8)* R4(PJ0)* R5(PJ3)* R6(PF13)* R7(PG1)* R8(PJ6)* R10(PE11)*

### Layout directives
net class MICROCONTROLLER: MD_CCI_I2C3.SCL, MD_CCI_I2C3.SDA, NetC97_1, NetC105_1, NetC261_1, NetC264_1, NetR382_2, NetR383_2, NetR384_2, NetR385_2, PA0, PA1, PA2, PA4, PA5, PA6, PA7, PA8, PA9, PA10, PA11, PA12, PA13, PA14, PA15_12, PB0, PB1, PB2, PB3, PB4, PB5, PB6, PB7, PB10, PB11, PB12, PB13, PB14, PB15, PC0, PC1, PC2, PC3, PC6, PC7, PC8, PC9, PC10, PC11, PC12, PD0, PD1, PD3, PD5, PD9, PD10, PD11, PD12, PD13, PD14, PD15, PE1, PE2, PE3, PE4, PE5, PE6, PE7, PE8, PE12, PE13, PE14, PE15, PF0, PF1, PF4, PF6, PF7, PF14, PG2, PG3, PG4, PG5, PG6, PG8, PG9, PG10, PG11, PG12, PG13, PG14, PG15, PH2, PH3, PH4, PH5, PH6, PH7, PH8, PH9, PH10, PH11, PH12, PH13, PH14, PH15, PI2, PI5, PI7, PI8, PI9, PI11, PK0, PK1, PK2, PK10, PK11, PK13

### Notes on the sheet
- ANALOG SWITCH
- RGB LEDS
- JDIGITAL
- LED MATRIX
- JANALOG
- TO PROCESSOR
- JSPI
- JMISC
- CAN PHY
- FAN
- JALPHA JBETA
- SWDIO
- SWCLK
- QWIIC

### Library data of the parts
C63 C65 C106-C108 = C0002-A.15: CAP CHIP 0201 1uF 20% 6.3V X5R; Manufacturer: Murata; Code Arduino: A5520
C64 C259 C286 C287 = C0037-A.14: CAP CHIP 0402 4.7uF 20% 6V3 X5R; Manufacturer: Hottech; Code Arduino: 0833
C97 C105 = C0003-A.15: CAP CHIP 0201 12pF 5% 25V C0G; Manufacturer: Murata; Code Arduino: C0003
C260 C262 C263 C265-C270 C272 C273 C275 C277 C279 C281 C282 C291 = C0113-A.6: CAP CHIP 0201 100nF 10% 10V X5R; Manufacturer: Samsung Electro-Mechanics; Code Arduino: C0113
C261 C264 = C0203-A.1: CAP CHIP 0201 6pF 0.25pF 25V C0G; Manufacturer: Murata; Code Arduino: C0203
C285 = C0202-A.1: CAP CHIP 0201 220pF 10% 50V X7R; Manufacturer: Murata; Code Arduino: C0202
C288 = C0158-A.3: CAP CHIP 0805 10uF 20% 50V X5R; Manufacturer: Murata Electronics; Code Arduino: C0158
L6 = I0028-A.10: FERRITE SMD 0402 120Ohm 25% 100MHz Ferrite 2A; Manufacturer: Murata; DC Resistance (DCR): 55mR; Code Arduino: I0028; Value: 120µH
L21 = I0019-A.10: INDUCTOR SMD 0806 2.2uH 1.2A; Manufacturer: Murata; DC Resistance (DCR): 138mR; Tolerance: 30%; Test Frequency: 1MHz; Code Arduino: A5528
LOVE = UT0013-A.6: Manufacturer: This is not a component
R181 R352 = R0146-A.21: RES CHIP 0201 100k 1% 1/20W; Manufacturer: Yageo; Power: 50mW; Temperature coefficient: 200ppm; Code Arduino: R0146
R218 R351 R382-R385 R434 R435 = R0140-A.21: as R140 on sheet MICROCONTROLLER
R371-R374 = R0151-A.21: RES CHIP 0201 4k7 1% 1/20W; Manufacturer: Yageo; Power: 50mW; Temperature coefficient: 200ppm; Code Arduino: A5521
R375 R376 = R0145-A.21: as R184 on sheet MICROCONTROLLER
TP35 TP67 TP68 TP70 TP71 TP90-TP92 = UT0013-A.6: Part Number: This is not a component
U3 = U0520-A.5: IC Cortex M33 250MHz, 4MB flash, 1.5MB RAM, TFBGA225 13x13mm; Manufacturer: ST; Code Arduino: U0520
Y3 = X0035-A.2: CRYSTAL 48MHz tolerance 10ppm stability 15ppm load 10pF, shunt 2pF, ESR 30R, 3.2x2.5mm; Manufacturer: ECS; Load Capacitance: 8pF; ESR (Equivalent Series Resistance): 30; Code Arduino: X0035
Y4 = X0003-A.5: CRYSTAL 32.768kHz 20ppm 12.5pF SMD 1.6x0.9mm; Manufacturer: Citizen FineDevice; Frequency Stability: 0.12%; Code Arduino: 0213; Series Resistance: 70kR

## Sheet LED.SchDoc: LED
size A3; Author: Silvio Navaretti; CompanyName: ARDUINO; DrawnBy: Silvio Navaretti; Engineer: Silvio Navaretti; Organization: ARDUINO; SheetNumber: 14; SheetTotal: 51; RevAuthor: Silvio Navaretti
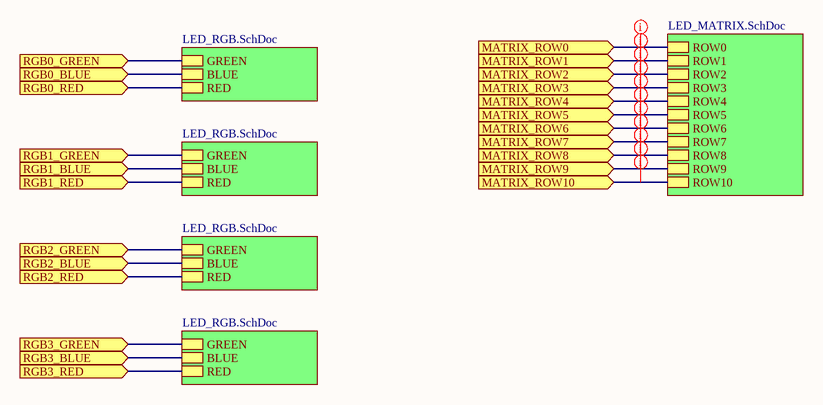
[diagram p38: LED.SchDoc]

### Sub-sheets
U_LED_MATRIX = LED_MATRIX.SchDoc: ROW0, ROW1, ROW2, ROW3, ROW4, ROW5, ROW6, ROW7, ROW8, ROW9, ROW10
U_LED_RGB = LED_RGB.SchDoc: GREEN, BLUE, RED
U_LED_RGB = LED_RGB.SchDoc: GREEN, BLUE, RED
U_LED_RGB = LED_RGB.SchDoc: GREEN, BLUE, RED
U_LED_RGB = LED_RGB.SchDoc: GREEN, BLUE, RED

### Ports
MATRIX_ROW0 (in), MATRIX_ROW1 (in), MATRIX_ROW2 (in), MATRIX_ROW3 (in), MATRIX_ROW4 (in), MATRIX_ROW5 (in), MATRIX_ROW6 (in), MATRIX_ROW7 (in), MATRIX_ROW8 (in), MATRIX_ROW9 (in), MATRIX_ROW10 (in), RGB0_BLUE (in), RGB0_GREEN (in), RGB0_RED (in), RGB1_BLUE (in), RGB1_GREEN (in), RGB1_RED (in), RGB2_BLUE (in), RGB2_GREEN (in), RGB2_RED (in), RGB3_BLUE (in), RGB3_GREEN (in), RGB3_RED (in)

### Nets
PC6: port RGB3_BLUE, sheet U_LED_RGB/BLUE
PD10: port RGB1_GREEN, sheet U_LED_RGB/GREEN
PD11: port RGB2_RED, sheet U_LED_RGB/RED
PG2: port RGB3_RED, sheet U_LED_RGB/RED
PG3: port RGB0_RED, sheet U_LED_RGB/RED
PG4: port RGB1_RED, sheet U_LED_RGB/RED
PG5: port RGB2_GREEN, sheet U_LED_RGB/GREEN
PG6: port RGB0_GREEN, sheet U_LED_RGB/GREEN
PG8: port RGB3_GREEN, sheet U_LED_RGB/GREEN
PH2: port MATRIX_ROW0, sheet U_LED_MATRIX/ROW0
PH3: port MATRIX_ROW1, sheet U_LED_MATRIX/ROW1
PH4: port MATRIX_ROW2, sheet U_LED_MATRIX/ROW2
PH5: port MATRIX_ROW3, sheet U_LED_MATRIX/ROW3
PH6: port MATRIX_ROW4, sheet U_LED_MATRIX/ROW4
PH7: port MATRIX_ROW5, sheet U_LED_MATRIX/ROW5
PH9: port MATRIX_ROW6, sheet U_LED_MATRIX/ROW6
PH10: port MATRIX_ROW7, sheet U_LED_MATRIX/ROW7
PH13: port MATRIX_ROW8, sheet U_LED_MATRIX/ROW8
PH14: port MATRIX_ROW9, sheet U_LED_MATRIX/ROW9
PH15: port MATRIX_ROW10, sheet U_LED_MATRIX/ROW10
PK0: port RGB2_BLUE, sheet U_LED_RGB/BLUE
PK1: port RGB1_BLUE, sheet U_LED_RGB/BLUE
PK2: port RGB0_BLUE, sheet U_LED_RGB/BLUE

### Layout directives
net class MICROCONTROLLER_MATRIX: PH2, PH3, PH4, PH5, PH6, PH7, PH9, PH10, PH13, PH14, PH15

## Sheet LED_MATRIX.SchDoc: LED MATRIX
size A3; Author: Silvio Navaretti; CompanyName: ARDUINO; DrawnBy: Silvio Navaretti; Engineer: Silvio Navaretti; Organization: ARDUINO; SheetNumber: 40; SheetTotal: 41; RevAuthor: Silvio Navaretti
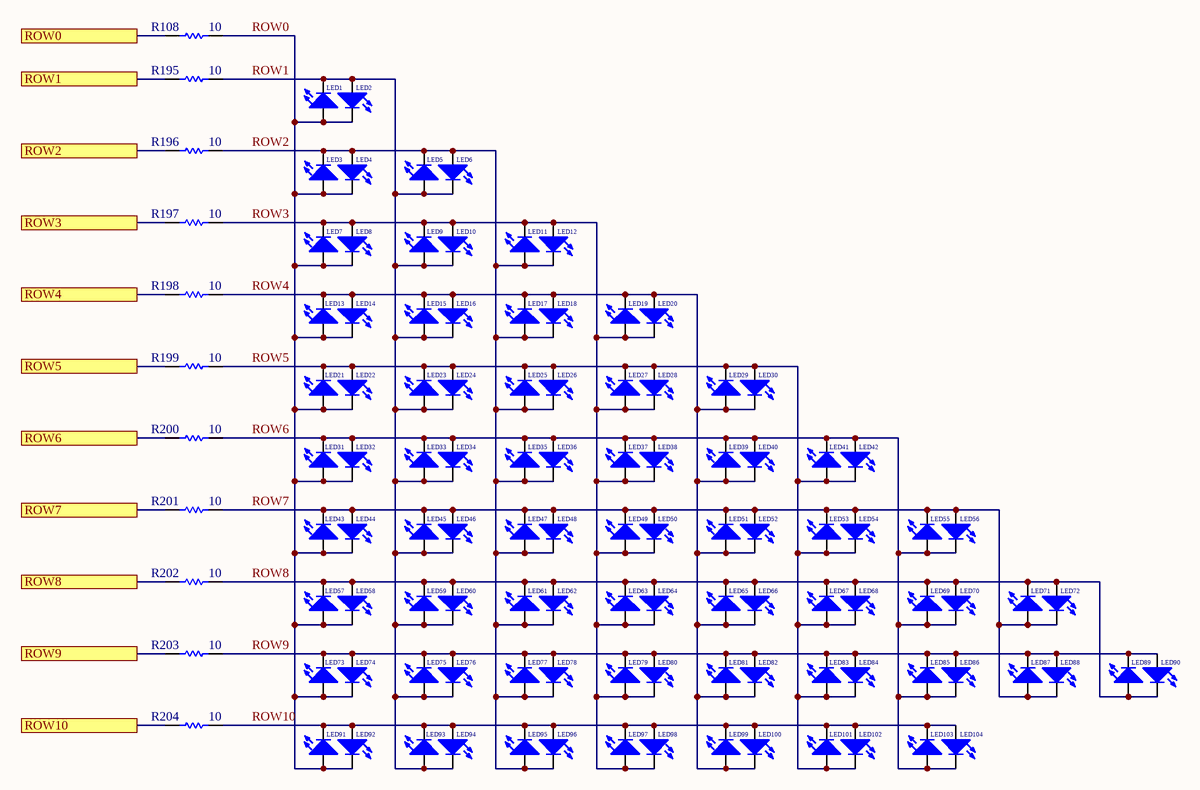
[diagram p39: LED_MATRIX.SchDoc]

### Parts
LED1  LTST-C191TBKT-5A  [LEDC1608X80N-AK]  (value not drawn)
LED2  LTST-C191TBKT-5A  [LEDC1608X80N-AK]  (value not drawn)
LED3  LTST-C191TBKT-5A  [LEDC1608X80N-AK]  (value not drawn)
LED4  LTST-C191TBKT-5A  [LEDC1608X80N-AK]  (value not drawn)
LED5  LTST-C191TBKT-5A  [LEDC1608X80N-AK]  (value not drawn)
LED6  LTST-C191TBKT-5A  [LEDC1608X80N-AK]  (value not drawn)
LED7  LTST-C191TBKT-5A  [LEDC1608X80N-AK]  (value not drawn)
LED8  LTST-C191TBKT-5A  [LEDC1608X80N-AK]  (value not drawn)
LED9  LTST-C191TBKT-5A  [LEDC1608X80N-AK]  (value not drawn)
LED10  LTST-C191TBKT-5A  [LEDC1608X80N-AK]  (value not drawn)
LED11  LTST-C191TBKT-5A  [LEDC1608X80N-AK]  (value not drawn)
LED12  LTST-C191TBKT-5A  [LEDC1608X80N-AK]  (value not drawn)
LED13  LTST-C191TBKT-5A  [LEDC1608X80N-AK]  (value not drawn)
LED14  LTST-C191TBKT-5A  [LEDC1608X80N-AK]  (value not drawn)
LED15  LTST-C191TBKT-5A  [LEDC1608X80N-AK]  (value not drawn)
LED16  LTST-C191TBKT-5A  [LEDC1608X80N-AK]  (value not drawn)
LED17  LTST-C191TBKT-5A  [LEDC1608X80N-AK]  (value not drawn)
LED18  LTST-C191TBKT-5A  [LEDC1608X80N-AK]  (value not drawn)
LED19  LTST-C191TBKT-5A  [LEDC1608X80N-AK]  (value not drawn)
LED20  LTST-C191TBKT-5A  [LEDC1608X80N-AK]  (value not drawn)
LED21  LTST-C191TBKT-5A  [LEDC1608X80N-AK]  (value not drawn)
LED22  LTST-C191TBKT-5A  [LEDC1608X80N-AK]  (value not drawn)
LED23  LTST-C191TBKT-5A  [LEDC1608X80N-AK]  (value not drawn)
LED24  LTST-C191TBKT-5A  [LEDC1608X80N-AK]  (value not drawn)
LED25  LTST-C191TBKT-5A  [LEDC1608X80N-AK]  (value not drawn)
LED26  LTST-C191TBKT-5A  [LEDC1608X80N-AK]  (value not drawn)
LED27  LTST-C191TBKT-5A  [LEDC1608X80N-AK]  (value not drawn)
LED28  LTST-C191TBKT-5A  [LEDC1608X80N-AK]  (value not drawn)
LED29  LTST-C191TBKT-5A  [LEDC1608X80N-AK]  (value not drawn)
LED30  LTST-C191TBKT-5A  [LEDC1608X80N-AK]  (value not drawn)
LED31  LTST-C191TBKT-5A  [LEDC1608X80N-AK]  (value not drawn)
LED32  LTST-C191TBKT-5A  [LEDC1608X80N-AK]  (value not drawn)
LED33  LTST-C191TBKT-5A  [LEDC1608X80N-AK]  (value not drawn)
LED34  LTST-C191TBKT-5A  [LEDC1608X80N-AK]  (value not drawn)
LED35  LTST-C191TBKT-5A  [LEDC1608X80N-AK]  (value not drawn)
LED36  LTST-C191TBKT-5A  [LEDC1608X80N-AK]  (value not drawn)
LED37  LTST-C191TBKT-5A  [LEDC1608X80N-AK]  (value not drawn)
LED38  LTST-C191TBKT-5A  [LEDC1608X80N-AK]  (value not drawn)
LED39  LTST-C191TBKT-5A  [LEDC1608X80N-AK]  (value not drawn)
LED40  LTST-C191TBKT-5A  [LEDC1608X80N-AK]  (value not drawn)
LED41  LTST-C191TBKT-5A  [LEDC1608X80N-AK]  (value not drawn)
LED42  LTST-C191TBKT-5A  [LEDC1608X80N-AK]  (value not drawn)
LED43  LTST-C191TBKT-5A  [LEDC1608X80N-AK]  (value not drawn)
LED44  LTST-C191TBKT-5A  [LEDC1608X80N-AK]  (value not drawn)
LED45  LTST-C191TBKT-5A  [LEDC1608X80N-AK]  (value not drawn)
LED46  LTST-C191TBKT-5A  [LEDC1608X80N-AK]  (value not drawn)
LED47  LTST-C191TBKT-5A  [LEDC1608X80N-AK]  (value not drawn)
LED48  LTST-C191TBKT-5A  [LEDC1608X80N-AK]  (value not drawn)
LED49  LTST-C191TBKT-5A  [LEDC1608X80N-AK]  (value not drawn)
LED50  LTST-C191TBKT-5A  [LEDC1608X80N-AK]  (value not drawn)
LED51  LTST-C191TBKT-5A  [LEDC1608X80N-AK]  (value not drawn)
LED52  LTST-C191TBKT-5A  [LEDC1608X80N-AK]  (value not drawn)
LED53  LTST-C191TBKT-5A  [LEDC1608X80N-AK]  (value not drawn)
LED54  LTST-C191TBKT-5A  [LEDC1608X80N-AK]  (value not drawn)
LED55  LTST-C191TBKT-5A  [LEDC1608X80N-AK]  (value not drawn)
LED56  LTST-C191TBKT-5A  [LEDC1608X80N-AK]  (value not drawn)
LED57  LTST-C191TBKT-5A  [LEDC1608X80N-AK]  (value not drawn)
LED58  LTST-C191TBKT-5A  [LEDC1608X80N-AK]  (value not drawn)
LED59  LTST-C191TBKT-5A  [LEDC1608X80N-AK]  (value not drawn)
LED60  LTST-C191TBKT-5A  [LEDC1608X80N-AK]  (value not drawn)
LED61  LTST-C191TBKT-5A  [LEDC1608X80N-AK]  (value not drawn)
LED62  LTST-C191TBKT-5A  [LEDC1608X80N-AK]  (value not drawn)
LED63  LTST-C191TBKT-5A  [LEDC1608X80N-AK]  (value not drawn)
LED64  LTST-C191TBKT-5A  [LEDC1608X80N-AK]  (value not drawn)
LED65  LTST-C191TBKT-5A  [LEDC1608X80N-AK]  (value not drawn)
LED66  LTST-C191TBKT-5A  [LEDC1608X80N-AK]  (value not drawn)
LED67  LTST-C191TBKT-5A  [LEDC1608X80N-AK]  (value not drawn)
LED68  LTST-C191TBKT-5A  [LEDC1608X80N-AK]  (value not drawn)
LED69  LTST-C191TBKT-5A  [LEDC1608X80N-AK]  (value not drawn)
LED70  LTST-C191TBKT-5A  [LEDC1608X80N-AK]  (value not drawn)
LED71  LTST-C191TBKT-5A  [LEDC1608X80N-AK]  (value not drawn)
LED72  LTST-C191TBKT-5A  [LEDC1608X80N-AK]  (value not drawn)
LED73  LTST-C191TBKT-5A  [LEDC1608X80N-AK]  (value not drawn)
LED74  LTST-C191TBKT-5A  [LEDC1608X80N-AK]  (value not drawn)
LED75  LTST-C191TBKT-5A  [LEDC1608X80N-AK]  (value not drawn)
LED76  LTST-C191TBKT-5A  [LEDC1608X80N-AK]  (value not drawn)
LED77  LTST-C191TBKT-5A  [LEDC1608X80N-AK]  (value not drawn)
LED78  LTST-C191TBKT-5A  [LEDC1608X80N-AK]  (value not drawn)
LED79  LTST-C191TBKT-5A  [LEDC1608X80N-AK]  (value not drawn)
LED80  LTST-C191TBKT-5A  [LEDC1608X80N-AK]  (value not drawn)
LED81  LTST-C191TBKT-5A  [LEDC1608X80N-AK]  (value not drawn)
LED82  LTST-C191TBKT-5A  [LEDC1608X80N-AK]  (value not drawn)
LED83  LTST-C191TBKT-5A  [LEDC1608X80N-AK]  (value not drawn)
LED84  LTST-C191TBKT-5A  [LEDC1608X80N-AK]  (value not drawn)
LED85  LTST-C191TBKT-5A  [LEDC1608X80N-AK]  (value not drawn)
LED86  LTST-C191TBKT-5A  [LEDC1608X80N-AK]  (value not drawn)
LED87  LTST-C191TBKT-5A  [LEDC1608X80N-AK]  (value not drawn)
LED88  LTST-C191TBKT-5A  [LEDC1608X80N-AK]  (value not drawn)
LED89  LTST-C191TBKT-5A  [LEDC1608X80N-AK]  (value not drawn)
LED90  LTST-C191TBKT-5A  [LEDC1608X80N-AK]  (value not drawn)
LED91  LTST-C191TBKT-5A  [LEDC1608X80N-AK]  (value not drawn)
LED92  LTST-C191TBKT-5A  [LEDC1608X80N-AK]  (value not drawn)
LED93  LTST-C191TBKT-5A  [LEDC1608X80N-AK]  (value not drawn)
LED94  LTST-C191TBKT-5A  [LEDC1608X80N-AK]  (value not drawn)
LED95  LTST-C191TBKT-5A  [LEDC1608X80N-AK]  (value not drawn)
LED96  LTST-C191TBKT-5A  [LEDC1608X80N-AK]  (value not drawn)
LED97  LTST-C191TBKT-5A  [LEDC1608X80N-AK]  (value not drawn)
LED98  LTST-C191TBKT-5A  [LEDC1608X80N-AK]  (value not drawn)
LED99  LTST-C191TBKT-5A  [LEDC1608X80N-AK]  (value not drawn)
LED100  LTST-C191TBKT-5A  [LEDC1608X80N-AK]  (value not drawn)
LED101  LTST-C191TBKT-5A  [LEDC1608X80N-AK]  (value not drawn)
LED102  LTST-C191TBKT-5A  [LEDC1608X80N-AK]  (value not drawn)
LED103  LTST-C191TBKT-5A  [LEDC1608X80N-AK]  (value not drawn)
LED104  LTST-C191TBKT-5A  [LEDC1608X80N-AK]  (value not drawn)
R108  value 10  [RES-0402]  (hidden comment: RC0402FR-0710RL)
R195  value 10  [RES-0402]  (hidden comment: RC0402FR-0710RL)
R196  value 10  [RES-0402]  (hidden comment: RC0402FR-0710RL)
R197  value 10  [RES-0402]  (hidden comment: RC0402FR-0710RL)
R198  value 10  [RES-0402]  (hidden comment: RC0402FR-0710RL)
R199  value 10  [RES-0402]  (hidden comment: RC0402FR-0710RL)
R200  value 10  [RES-0402]  (hidden comment: RC0402FR-0710RL)
R201  value 10  [RES-0402]  (hidden comment: RC0402FR-0710RL)
R202  value 10  [RES-0402]  (hidden comment: RC0402FR-0710RL)
R203  value 10  [RES-0402]  (hidden comment: RC0402FR-0710RL)
R204  value 10  [RES-0402]  (hidden comment: RC0402FR-0710RL)

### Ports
ROW0, ROW1, ROW2, ROW3, ROW4, ROW5, ROW6, ROW7, ROW8, ROW9, ROW10

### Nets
PH2: R108.2 ; port ROW0
PH3: R195.2 ; port ROW1
PH4: R196.2 ; port ROW2
PH5: R197.2 ; port ROW3
PH6: R198.2 ; port ROW4
PH7: R199.2 ; port ROW5
PH9: R200.2 ; port ROW6
PH10: R201.2 ; port ROW7
PH13: R202.2 ; port ROW8
PH14: R203.2 ; port ROW9
PH15: R204.2 ; port ROW10
ROW0: LED1.A LED2.C LED3.A LED4.C LED7.A LED8.C LED13.A LED14.C LED21.A LED22.C LED31.A LED32.C LED43.A LED44.C LED57.A LED58.C LED73.A LED74.C LED91.A LED92.C R108.1  [project net ROW0_40]
ROW1: LED1.C LED2.A LED5.A LED6.C LED9.A LED10.C LED15.A LED16.C LED23.A LED24.C LED33.A LED34.C LED45.A LED46.C LED59.A LED60.C LED75.A LED76.C LED93.A LED94.C R195.1  [project net ROW1_40]
ROW2: LED3.C LED4.A LED5.C LED6.A LED11.A LED12.C LED17.A LED18.C LED25.A LED26.C LED35.A LED36.C LED47.A LED48.C LED61.A LED62.C LED77.A LED78.C LED95.A LED96.C R196.1  [project net ROW2_40]
ROW3: LED7.C LED8.A LED9.C LED10.A LED11.C LED12.A LED19.A LED20.C LED27.A LED28.C LED37.A LED38.C LED49.A LED50.C LED63.A LED64.C LED79.A LED80.C LED97.A LED98.C R197.1  [project net ROW3_40]
ROW4: LED13.C LED14.A LED15.C LED16.A LED17.C LED18.A LED19.C LED20.A LED29.A LED30.C LED39.A LED40.C LED51.A LED52.C LED65.A LED66.C LED81.A LED82.C LED99.A LED100.C R198.1  [project net ROW4_40]
ROW5: LED21.C LED22.A LED23.C LED24.A LED25.C LED26.A LED27.C LED28.A LED29.C LED30.A LED41.A LED42.C LED53.A LED54.C LED67.A LED68.C LED83.A LED84.C LED101.A LED102.C R199.1  [project net ROW5_40]
ROW6: LED31.C LED32.A LED33.C LED34.A LED35.C LED36.A LED37.C LED38.A LED39.C LED40.A LED41.C LED42.A LED55.A LED56.C LED69.A LED70.C LED85.A LED86.C LED103.A LED104.C R200.1  [project net ROW6_40]
ROW7: LED43.C LED44.A LED45.C LED46.A LED47.C LED48.A LED49.C LED50.A LED51.C LED52.A LED53.C LED54.A LED55.C LED56.A LED71.A LED72.C LED87.A LED88.C R201.1  [project net ROW7_40]
ROW8: LED57.C LED58.A LED59.C LED60.A LED61.C LED62.A LED63.C LED64.A LED65.C LED66.A LED67.C LED68.A LED69.C LED70.A LED71.C LED72.A LED89.A LED90.C R202.1  [project net ROW8_40]
ROW9: LED73.C LED74.A LED75.C LED76.A LED77.C LED78.A LED79.C LED80.A LED81.C LED82.A LED83.C LED84.A LED85.C LED86.A LED87.C LED88.A LED89.C LED90.A R203.1  [project net ROW9_40]
ROW10: LED91.C LED92.A LED93.C LED94.A LED95.C LED96.A LED97.C LED98.A LED99.C LED100.A LED101.C LED102.A LED103.C LED104.A R204.1  [project net ROW10_40]

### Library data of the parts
LED1-LED104 = L0040-A.2: LED SMD 0603 BLUE 468nm, water clear, 11-45 mcd, 138 deg; Manufacturer: Liteon; Code Arduino: L0040
R108 R195-R204 = R0170-A.23: RES CHIP 0402 10R 1% 1/16W; Manufacturer: YAGEO; Code Arduino: R0170; Power: 62.5mW; Temperature coefficient: 200ppm

## Sheet LED_RGB.SchDoc: LED RGB
size A3; Author: Silvio Navaretti; CompanyName: ARDUINO; DrawnBy: Silvio Navaretti; Engineer: Silvio Navaretti; Organization: ARDUINO; SheetNumber: 16; SheetTotal: 51; RevAuthor: Silvio Navaretti
Used 4 times, as channels U_MICROCONTROLLER/U_LED/U_LED_RGB, U_MICROCONTROLLER/U_LED/U_LED_RGB, U_MICROCONTROLLER/U_LED/U_LED_RGB, U_MICROCONTROLLER/U_LED/U_LED_RGB. Parts and nets are listed once, with the designators drawn on the sheet.
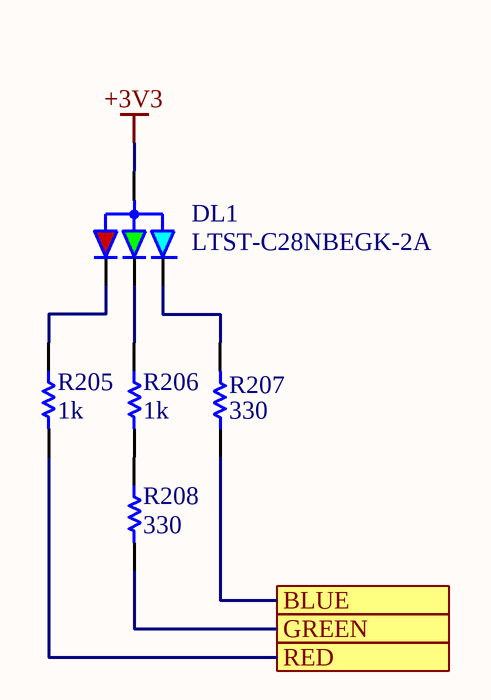
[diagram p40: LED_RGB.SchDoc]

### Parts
DL1  LTST-C28NBEGK-2A  [SMLP34RGB2W]
R205  value 1k  [RES-0201]  (hidden comment: RC0201FR-071KL)
R206  value 1k  [RES-0201]  (hidden comment: RC0201FR-071KL)
R207  value 330  [RES-0201]  (hidden comment: AC0201FR-07330RL)
R208  value 330  [RES-0201]  (hidden comment: AC0201FR-07330RL)

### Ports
BLUE, GREEN, RED

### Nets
+3V3: DL1.1(ANODE)
BLUE: R207.1 ; port BLUE
GREEN: R208.2 ; port GREEN
RED: R205.2 ; port RED
NetDL1_2: DL1.2(RED_C) R205.1
NetDL1_3: DL1.3(BLUE_C) R207.2
NetDL1_4: DL1.4(GREEN_C) R206.1
NetR206_2: R206.2 R208.1

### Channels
U_MICROCONTROLLER/U_LED/U_LED_RGB: designators end in _1; ports BLUE=PK2 GREEN=PG6 RED=PG3
U_MICROCONTROLLER/U_LED/U_LED_RGB: designators end in _2; ports BLUE=PK1 GREEN=PD10 RED=PG4
U_MICROCONTROLLER/U_LED/U_LED_RGB: designators end in _3; ports BLUE=PK0 GREEN=PG5 RED=PD11
U_MICROCONTROLLER/U_LED/U_LED_RGB: designators end in _4; ports BLUE=PC6 GREEN=PG8 RED=PG2

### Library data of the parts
DL1 = L0014-A.13: LED RGB DIFFUSED PICOLED SMD; Manufacturer: Liteon; Dominant Wavelength: 470nm; Forward Current: 20mA; Code Arduino: A5469; Luminous Intensity: 45mcd; Forward Voltage: 3V; Lens Color: White; Lens Style: Rectangular; Test Current: 5mA
R205 R206 = R0195-A.22: as R412 on sheet MICROCONTROLLER
R207 = R0149-A.21: RES CHIP 0201 330R 1% 1/20W; Manufacturer: Yageo; Power: 50mW; Code Arduino: R0149; Temperature coefficient: 200ppm
R208 = R0149-A.21: RES CHIP 0201 330R 1% 1/20W; Manufacturer: Yageo; Power: 50mW; Temperature coefficient: 200ppm; Code Arduino: R0149

## Sheet QWIIC.SchDoc: QWIIC
size A3; SheetNumber: 13; SheetTotal: 51
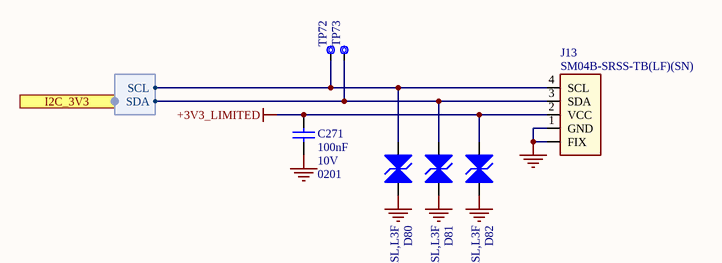
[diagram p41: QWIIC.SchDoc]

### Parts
C271  value 100nF  Voltage: 10V  Case Code (Imperial): 0201  [CAP-0201]  (hidden comment: CL03A104KP3NNNC)
D80  DF2B7ASL,L3F  [DF2B7ASL,L3F]
D81  DF2B7ASL,L3F  [DF2B7ASL,L3F]
D82  DF2B7ASL,L3F  [DF2B7ASL,L3F]
J13  SM04B-SRSS-TB(LF)(SN)  [SM04B-SRSS-TB(LF)(SN)-Footprint-1]
TP72  Test point 1.00mm  [TP-1.00MM]  (value not drawn)  (no BOM)
TP73  Test point 1.00mm  [TP-1.00MM]  (value not drawn)  (no BOM)

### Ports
I2C_3V3 (harness I2C)

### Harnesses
I2C: SDA, SCL

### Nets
+3V3_LIMITED: C271.2 D82.2(A2) J13.2(VCC)
GND: C271.1 D80.1(A1) D81.1(A1) D82.1(A1) J13.1(GND) J13.FIX
PA8: D80.2(A2) J13.4(SCL) TP72.X ; port I2C_3V3.SCL
PC9: D81.2(A2) J13.3(SDA) TP73.X ; port I2C_3V3.SDA

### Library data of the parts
C271 = C0113-A.6: as C260 on sheet STM32
D80-D82 = D0099-5: TVS BIDIRECTIONAL SMD Vr 5.5V, Vbr min 5.8V, 0.62x0.32mm; Manufacturer: TOSHIBA; Vforward max: 0V; Ireverse max: 1µA; Power max: 80W; Code Arduino: D0099; Vreverse max: 20V
J13 = J0005-A.3: CONN JST SH 1mm 4POS HORIZONTAL TIN QWIIC; Code Arduino: J0005
TP72 TP73 = UT0013-A.6: Part Number: This is not a component

## Sheet ANALOG_SWITCH.SchDoc: ANALOG SWITCH
size A3; SheetNumber: 18; SheetTotal: 50
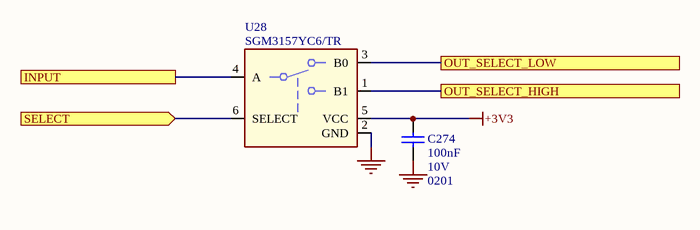
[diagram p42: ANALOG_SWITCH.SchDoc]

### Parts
C274  value 100nF  Voltage: 10V  Case Code (Imperial): 0201  [CAP-0201]  (hidden comment: CL03A104KP3NNNC)
U28  SGM3157YC6/TR  [TSOP65P210X110-6N]

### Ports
INPUT, OUT_SELECT_HIGH, OUT_SELECT_LOW, SELECT (in)

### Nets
+3V3: C274.2 U28.4(A) U28.5(VCC) ; port INPUT
GND: C274.1 U28.2(GND)
PI8: U28.6(SELECT) ; port SELECT
NetC107_2: U28.3(B0) ; port OUT_SELECT_LOW
NetU28_1: U28.1(B1) ; port OUT_SELECT_HIGH

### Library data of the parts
C274 = C0113-A.6: as C260 on sheet STM32
U28 = U0174-A.3: IC SPDT,max 25R at VCC 4.5V tPD 1.2ns VCC 1.65V to 5V Iq max 10uA SOT363; Manufacturer: SG Micro; Code Arduino: U0174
